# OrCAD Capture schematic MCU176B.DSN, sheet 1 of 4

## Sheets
1 1_RF: size A3; title: LP-EM-CC2755P20
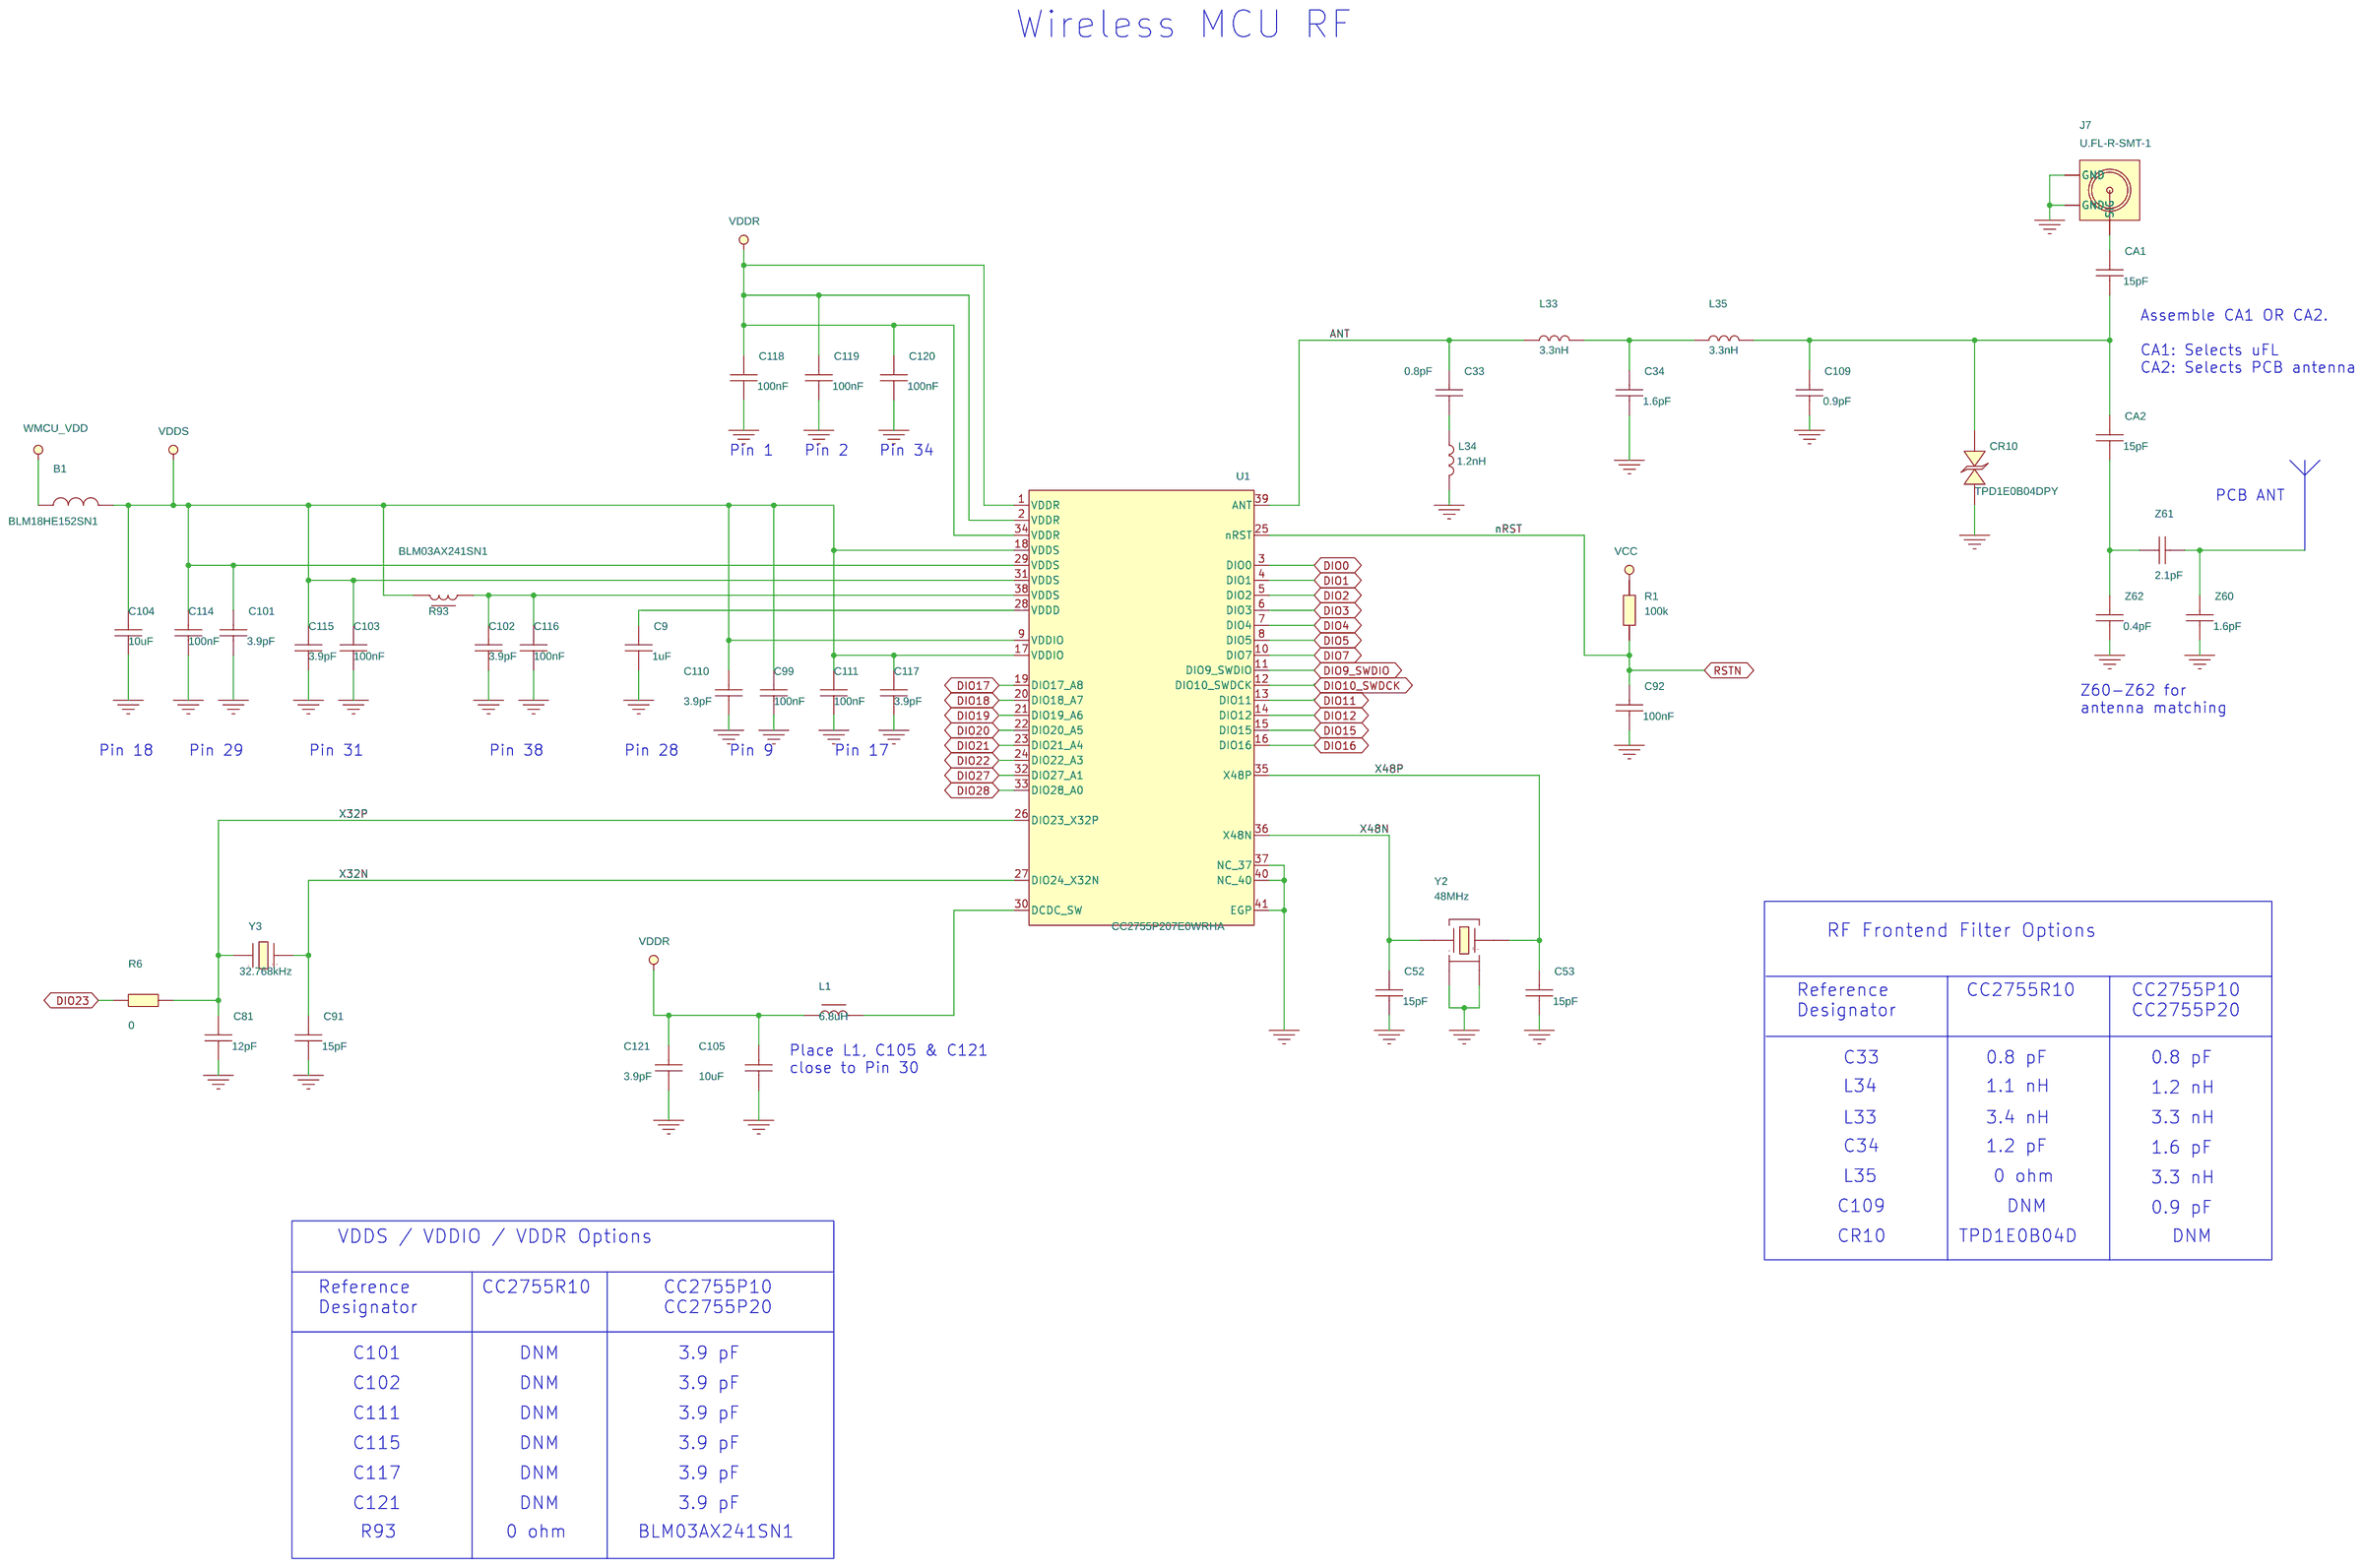
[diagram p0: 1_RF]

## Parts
B1  BLM18HE152SN1  [FIL_BLM18HE152SN1DN]
C9  1uF  [CAPC1005X60A2N]
C33  0.8pF  [CAPC0603X35B2N]
C34  1.6pF  [CAPC0603X35B2N]
C52  15pF  [CAPC0603X35B2N]
C53  15pF  [CAPC0603X35B2N]
C81  12pF  [CAPC0603X35B2N]
C91  15pF  [CAPC0603X35B2N]
C92  100nF  [CAPC0603X35B2N]
C99  100nF  [CAPC0603X35B2N]
C101  3.9pF  [CAPC0603X35B2N]
C102  3.9pF  [CAPC0603X35B2N]
C103  100nF  [CAPC0603X35B2N]
C104  10uF  [CAPC1608X100A2N]
C105  10uF  [CAPC1608X100A2N]
C109  0.9pF  [CAPC0603X35B2N]
C110  3.9pF  [CAPC0603X35B2N]
C111  100nF  [CAPC0603X35B2N]
C114  100nF  [CAPC0603X35B2N]
C115  3.9pF  [CAPC0603X35B2N]
C116  100nF  [CAPC0603X35B2N]
C117  3.9pF  [CAPC0603X35B2N]
C118  100nF  [CAPC0603X35B2N]
C119  100nF  [CAPC0603X35B2N]
C120  100nF  [CAPC0603X35B2N]
C121  3.9pF  [CAPC0603X35B2N]
CA1  15pF  [CAPC0603X35B2N]
CA2  15pF  [CAPC0603X35B2N]
CR10  TPD1E0B04DPY  [SON65P100X60X45-2A2N]
J7  U.FL-R-SMT-1  [HIROSE_UFLRSMT_A2N]
L1  6.8uH  [INDC2012X150A2N]
L33  3.3nH  [INDC0603X33A2N]
L34  1.2nH  [INDC0603X33A2N]
L35  3.3nH  [INDC0603X33A2N]
R1  100k  [RESC0603X35B2N]
R6  0  [RESC0603X35B2N]
R93  BLM03AX241SN1  [FILC0603X33A2N]
U1  CC2755P207E0WRHA  [QFNFC50P600X600X100-41C2N]
Y2  48MHz  [OSCCC200X160X50-4B2N]
Y3  32.768kHz  [XTAL_FC2012AA_A2N]
Z60  1.6pF  [CAPC0603X35B2N]
Z61  2.1pF  [CAPC0603X35B2N]
Z62  0.4pF  [CAPC0603X35B2N]

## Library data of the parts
B1 = FILTER_2PIN: FILTER, EMI, FERRITE BEAD, 1.5k@100MHz, -25%/+25%, -55DEGC/+125DEGC, 0603, SMD; ALT_SYMBOLS: FIL_BLM18HE152SN1DL,FIL_BLM18HE152SN1DM; Additional Datasheet URL: https://pim.murata.com/en-us/pim/details?partNum=BLM18HE152SN1%23; Budgetary Price: .07 EUR; CLASS: DISCRETE; Country of Origin: Japan; Datasheet URL: https://pim.murata.com/asset/pim4/ferriteBeadInductortypefilter/ENFA0004_PDF_FERRITEBEADINDUCTORTYPEFILTER?lastModifiedDatetime=20250707191219; Frequency: 100MHz; Impedance: 1.5k; Inductance: N/A; Lead Time: 8; Mass: 0.006g; Maximum Operating Temperature: +125DEGC; Maximum Tolerance: +25%; Minimum Operating Temperature: -55DEGC; Minimum Tolerance: -25%; Mounting Type: SMD; NOTEfied URL: https://webinterface.notefied-dynamic-precision.com/item/7304126; PCB Package: 0603; Packing Size: 4000; Packing Type: Tape & Reel; Part Number: 04-00470; Part Type: Filter|EMI|FERRITE BEAD|0603; REACH/SVHC Compliance: Compliant; REACH/SVHC Details: SVHC List Version Jan 23, 2024 (240); REACH/SVHC Source: REACH Declaration; REACH/SVHC Status: Unaffected; ROHS: Compliant; Rated Current: 0.5A; Rated Voltage: N/A; Status: Released; Texas Part Status: Under Review; Type: Filter; Vendor: MURATA; Vendor Part Number: BLM18HE152SN1D; Vendor Part Status: Active
C9 = CAPACITOR: CAPACITOR, CERAMIC X7R, 1uF, -10%/+10%, 10V, -55DEGC/+125DEGC, 0402, SMD; ALT_SYMBOLS: CAPC1005X60A2L,CAPC1005X60A2M; Additional Datasheet URL: https://pim.murata.com/en-us/pim/details?partNum=GRM155Z71A105KE01%23; Budgetary Price: .01854 USD; Country of Origin: China, Japan, Philippines, Singapore, Thailand; Datasheet URL: https://pim.murata.com/asset/pim4/ceramicCapacitorSMD/GRM155Z71A105KE01-01A-EN_PDF_CERAMICCAPACITORSMD?lastModifiedDatetime=20250813144905; Dielectric Type: X7R; FPLIST: CAPC1005X60A2N,CAPC1005X60B2N; Lead Time: 12; Mass: 0.0016g; Maximum Operating Temperature: +125DEGC; Maximum Tolerance: +10%; Minimum Operating Temperature: -55DEGC; Minimum Tolerance: -10%; Mounting Type: SMD; NOTEfied URL: https://webinterface.notefied-dynamic-precision.com/item/34840285; PCB Package: 0402; Packing Size: 10000; Packing Type: Tape & Reel; Part Number: 02-10417; Part Type: Capacitor|CERAMIC|0402|STANDARD; REACH/SVHC Compliance: Compliant; REACH/SVHC Details: SVHC List Version Jan 23, 2024 (240); REACH/SVHC Source: REACH Declaration; REACH/SVHC Status: Unaffected; ROHS: Compliant; Rated Voltage: 10V; Status: Released; Texas Part Status: Under Review; Type: Capacitor; Vendor: MURATA; Vendor Part Number: GRM155Z71A105KE01D; Vendor Part Status: Active
C33 = CAPACITOR: CAPACITOR, CERAMIC C0G/NP0, 0.8pF, -0.1pF/+0.1pF, 50V, -55DEGC/+125DEGC, 0201, SMD; ALT_SYMBOLS: CAPC0603X35B2L,CAPC0603X35B2M; Additional Datasheet URL: https://pim.murata.com/en-us/pim/details?partNum=GRM0335C1HR80BA01%23; Budgetary Price: .00272 USD; Country of Origin: China, Japan, Philippines, Singapore, Thailand; Datasheet URL: https://pim.murata.com/asset/pim4/ceramicCapacitorSMD/GRM0335C1HR80BA01-01A-EN_PDF_CERAMICCAPACITORSMD?lastModifiedDatetime=20250813140832; Dielectric Type: C0G/NP0; Lead Time: 11; Mass: 0.00033g; Maximum Operating Temperature: +125DEGC; Maximum Tolerance: +0.1pF; Minimum Operating Temperature: -55DEGC; Minimum Tolerance: -0.1pF; Mounting Type: SMD; NOTEfied URL: https://webinterface.notefied-dynamic-precision.com/item/7272565; PCB Package: 0201; Packing Size: 50000; Packing Type: Tape & Reel; Part Number: 02-06122; Part Type: Capacitor|CERAMIC|0201|STANDARD; REACH/SVHC Compliance: Compliant; REACH/SVHC Details: SVHC List Version Jan 23, 2024 (240); REACH/SVHC Source: REACH Declaration; REACH/SVHC Status: Unaffected; ROHS: Compliant; Rated Voltage: 50V; Status: Released; Texas Part Status: Under Review; Type: Capacitor; Vendor: MURATA; Vendor Part Number: GRM0335C1HR80BA01J; Vendor Part Status: Active
C34 Z60 = CAPACITOR: CAPACITOR, CERAMIC C0G/NP0, 1.6pF, -0.1pF/+0.1pF, 50V, -55DEGC/+125DEGC, 0201, SMD; ALT_SYMBOLS: CAPC0603X35B2L,CAPC0603X35B2M; Additional Datasheet URL: https://pim.murata.com/en-us/pim/details?partNum=GRM0335C1H1R6BA01%23; Budgetary Price: .00215 USD; Country of Origin: China, Japan, Philippines, Singapore, Thailand; Datasheet URL: https://pim.murata.com/asset/pim4/ceramicCapacitorSMD/GRM0335C1H1R6BA01-01A-EN_PDF_CERAMICCAPACITORSMD?lastModifiedDatetime=20250813140550; Dielectric Type: C0G/NP0; Lead Time: 84; Mass: 0.00033g; Maximum Operating Temperature: +125DEGC; Maximum Tolerance: +0.1pF; Minimum Operating Temperature: -55DEGC; Minimum Tolerance: -0.1pF; Mounting Type: SMD; NOTEfied URL: https://webinterface.notefied-dynamic-precision.com/item/7272585; PCB Package: 0201; Packing Size: 50000; Packing Type: Tape & Reel; Part Number: 02-06130; Part Type: Capacitor|CERAMIC|0201|STANDARD; REACH/SVHC Compliance: Compliant; REACH/SVHC Details: SVHC List Version Jan 23, 2024 (240); REACH/SVHC Source: REACH Declaration; REACH/SVHC Status: Unaffected; ROHS: Compliant; Rated Voltage: 50V; Status: Released; Texas Part Status: Under Review; Type: Capacitor; Vendor: MURATA; Vendor Part Number: GRM0335C1H1R6BA01J; Vendor Part Status: Active
C52 C53 C91 = CAPACITOR: CAPACITOR, CERAMIC C0G/NP0, 15pF, -2%/+2%, 50V, -55DEGC/+125DEGC, 0201, SMD; ALT_SYMBOLS: CAPC0603X35B2L,CAPC0603X35B2M; Additional Datasheet URL: https://pim.murata.com/en-us/pim/details?partNum=GRM0335C1H150GA01%23; Budgetary Price: .0032 USD; Country of Origin: China, Japan, Philippines, Singapore, Thailand; Datasheet URL: https://pim.murata.com/asset/pim4/ceramicCapacitorSMD/GRM0335C1H150GA01-01A-EN_PDF_CERAMICCAPACITORSMD?lastModifiedDatetime=20250813140536; Dielectric Type: C0G/NP0; Lead Time: 11; Mass: 0.00033g; Maximum Operating Temperature: +125DEGC; Maximum Tolerance: +2%; Minimum Operating Temperature: -55DEGC; Minimum Tolerance: -2%; Mounting Type: SMD; NOTEfied URL: https://webinterface.notefied-dynamic-precision.com/item/20744949; PCB Package: 0201; Packing Size: 15000; Packing Type: Tape & Reel; Part Number: 02-09323; Part Type: Capacitor|CERAMIC|0201|STANDARD; REACH/SVHC Compliance: Compliant; REACH/SVHC Details: SVHC List Version Jan 23, 2024 (240); REACH/SVHC Source: REACH Declaration; REACH/SVHC Status: Unaffected; ROHS: Compliant; Rated Voltage: 50V; Status: Released; Texas Part Status: Under Review; Type: Capacitor; Vendor: MURATA; Vendor Part Number: GRM0335C1H150GA01D; Vendor Part Status: Active
C81 = CAPACITOR: CAPACITOR, CERAMIC C0G/NP0, 12pF, -5%/+5%, 50V, -55DEGC/+125DEGC, 0201, SMD; ALT_SYMBOLS: CAPC0603X35B2L,CAPC0603X35B2M; Additional Datasheet URL: https://pim.murata.com/en-us/pim/details?partNum=GRM0335C1H120JA01%23; Budgetary Price: .0024 USD; Country of Origin: China, Japan, Philippines, Singapore, Thailand; Datasheet URL: https://pim.murata.com/asset/pim4/ceramicCapacitorSMD/GRM0335C1H120JA01-01A-EN_PDF_CERAMICCAPACITORSMD?lastModifiedDatetime=20250813140532; Dielectric Type: C0G/NP0; Lead Time: 11; Mass: 0.00033g; Maximum Operating Temperature: +125DEGC; Maximum Tolerance: +5%; Minimum Operating Temperature: -55DEGC; Minimum Tolerance: -5%; Mounting Type: SMD; NOTEfied URL: https://webinterface.notefied-dynamic-precision.com/item/20764951; PCB Package: 0201; Packing Size: 15000; Packing Type: Tape & Reel; Part Number: 02-09326; Part Type: Capacitor|CERAMIC|0201|STANDARD; REACH/SVHC Compliance: Compliant; REACH/SVHC Details: SVHC List Version Jan 23, 2024 (240); REACH/SVHC Source: REACH Declaration; REACH/SVHC Status: Unaffected; ROHS: Compliant; Rated Voltage: 50V; Status: Released; Texas Part Status: Under Review; Type: Capacitor; Vendor: MURATA; Vendor Part Number: GRM0335C1H120JA01D; Vendor Part Status: Active
C92 C99 C103 C111 C114 C116 C118-C120 = CAPACITOR: CAPACITOR, CERAMIC X7S, 100nF, -10%/+10%, 16V, -55DEGC/+125DEGC, 0201, SMD; ALT_SYMBOLS: CAPC0603X35B2L,CAPC0603X35B2M; Additional Datasheet URL: https://pim.murata.com/en-us/pim/details?partNum=GRM033C71C104KE14%23; Budgetary Price: .00785 EUR; Country of Origin: China, Japan, Philippines, Singapore, Thailand; Datasheet URL: https://pim.murata.com/asset/pim4/ceramicCapacitorSMD/GRM033C71C104KE14-01A-EN_PDF_CERAMICCAPACITORSMD?lastModifiedDatetime=20250813141327; Dielectric Type: X7S; Lead Time: 11; Mass: 0.00033g; Maximum Operating Temperature: +125DEGC; Maximum Tolerance: +10%; Minimum Operating Temperature: -55DEGC; Minimum Tolerance: -10%; Mounting Type: SMD; NOTEfied URL: https://webinterface.notefied-dynamic-precision.com/item/20463738; PCB Package: 0201; Packing Size: 15000; Packing Type: Tape & Reel; Part Number: 02-09228; Part Type: Capacitor|CERAMIC|0201|STANDARD; REACH/SVHC Compliance: Compliant; REACH/SVHC Details: SVHC List Version Jan 23, 2024 (240); REACH/SVHC Source: REACH Declaration & Material Declaration; REACH/SVHC Status: Unaffected; ROHS: Compliant; Rated Voltage: 16V; Status: Released; Texas Part Number: TEXAS_00001; Texas Part Status: Under Review; Type: Capacitor; Vendor: MURATA; Vendor Part Number: GRM033C71C104KE14D; Vendor Part Status: Active
C101 C102 C110 C115 C117 C121 = CAPACITOR: CAPACITOR, CERAMIC C0G/NP0, 3.9pF, -0.25pF/+0.25pF, 25V, -55DEGC/+125DEGC, 0201, SMD; ALT_SYMBOLS: CAPC0603X35B2L,CAPC0603X35B2M; Additional Datasheet URL: https://search.kyocera-avx.com/product/KGM03ACG1E3R9CH; Budgetary Price: .09832 USD; Country of Origin: Missing Info; Datasheet URL: https://datasheets.kyocera-avx.com/C0GNP0-KGM.pdf; Dielectric Type: C0G/NP0; Lead Time: 16; Mass: 0.000228g; Maximum Operating Temperature: +125DEGC; Maximum Tolerance: +0.25pF; Minimum Operating Temperature: -55DEGC; Minimum Tolerance: -0.25pF; Mounting Type: SMD; NOTEfied URL: https://webinterface.notefied-dynamic-precision.com/item/7266918; Notes: Old ordering code: 02013A3R9CAT2A.; PCB Package: 0201; Packing Size: 15000; Packing Type: Tape & Reel; Part Number: 02-04271; Part Type: Capacitor|CERAMIC|0201|STANDARD; ROHS: Compliant; Rated Voltage: 25V; Status: Released; Type: Capacitor; Vendor: KYOCERA AVX; Vendor Part Number: KGM03ACG1E3R9CH; Vendor Part Status: Active
C104 C105 = CAPACITOR: CAPACITOR, CERAMIC X7T, 10uF, -20%/+20%, 10V, -55DEGC/+125DEGC, 0603, SMD; ALT_SYMBOLS: CAPC1608X100A2L,CAPC1608X100A2M; Additional Datasheet URL: https://pim.murata.com/en-us/pim/details?partNum=GRM188D71A106MA73%23; Country of Origin: China, Japan, Philippines, Singapore, Thailand; Datasheet URL: https://pim.murata.com/asset/pim4/ceramicCapacitorSMD/GRM188D71A106MA73-01A-EN_PDF_CERAMICCAPACITORSMD?lastModifiedDatetime=20250813150623; Dielectric Type: X7T; Mass: 0.0091g; Maximum Operating Temperature: +125DEGC; Maximum Tolerance: +20%; Minimum Operating Temperature: -55DEGC; Minimum Tolerance: -20%; Mounting Type: SMD; NOTEfied URL: https://webinterface.notefied-dynamic-precision.com/item/46681190; PCB Package: 0603; Packing Size: 4000; Packing Type: Tape & Reel; Part Number: 02-10942; Part Type: Capacitor|CERAMIC|0603|STANDARD; REACH/SVHC Details: SVHC List Version; ROHS: Compliant; Rated Voltage: 10V; Status: Released; Type: Capacitor; Vendor: MURATA; Vendor Part Number: GRM188D71A106MA73D; Vendor Part Status: Active
C109 = CAPACITOR: CAPACITOR, CERAMIC C0G/NP0, 0.9pF, -0.1pF/+0.1pF, 50V, -55DEGC/+125DEGC, 0201, SMD; ALT_SYMBOLS: CAPC0603X35B2L,CAPC0603X35B2M; Additional Datasheet URL: https://pim.murata.com/en-us/pim/details?partNum=GRM0335C1HR90BA01%23; Budgetary Price: .002 USD; Country of Origin: China, Japan, Philippines, Singapore, Thailand; Datasheet URL: https://pim.murata.com/asset/pim4/ceramicCapacitorSMD/GRM0335C1HR90BA01-01A-EN_PDF_CERAMICCAPACITORSMD?lastModifiedDatetime=20250813140833; Dielectric Type: C0G/NP0; Lead Time: 11; Mass: 0.00033g; Maximum Operating Temperature: +125DEGC; Maximum Tolerance: +0.1pF; Minimum Operating Temperature: -55DEGC; Minimum Tolerance: -0.1pF; Mounting Type: SMD; NOTEfied URL: https://webinterface.notefied-dynamic-precision.com/item/7272566; PCB Package: 0201; Packing Size: 50000; Packing Type: Tape & Reel; Part Number: 02-06123; Part Type: Capacitor|CERAMIC|0201|STANDARD; REACH/SVHC Compliance: Compliant; REACH/SVHC Details: SVHC List Version Jan 23, 2024 (240); REACH/SVHC Source: REACH Declaration; REACH/SVHC Status: Unaffected; ROHS: Compliant; Rated Voltage: 50V; Status: Released; Texas Part Status: Under Review; Type: Capacitor; Vendor: MURATA; Vendor Part Number: GRM0335C1HR90BA01J; Vendor Part Status: Active
CA1 CA2 = CAPACITOR: CAPACITOR, CERAMIC CH(JIS), 15pF, -5%/+5%, 50V, -55DEGC/+125DEGC, 0201, SMD; ALT_SYMBOLS: CAPC0603X35B2L,CAPC0603X35B2M; Additional Datasheet URL: https://www.murata.com/en-us/products/productdetail?partno=GRM0332C1H150JA01%23; Country of Origin: China, Philippines; Datasheet URL: https://search.murata.co.jp/Ceramy/image/img/A01X/G101/ENG/GRM0332C1H150JA01-01A.pdf; Dielectric Type: CH(JIS); Mass: 0.00033g; Maximum Operating Temperature: +125DEGC; Maximum Tolerance: +5%; Minimum Operating Temperature: -55DEGC; Minimum Tolerance: -5%; Mounting Type: SMD; NOTEfied URL: https://webinterface.notefied-dynamic-precision.com/item/7272608; PCB Package: 0201; Packing Size: 15000; Packing Type: Tape & Reel; Part Number: 02-06059; Part Type: Capacitor|CERAMIC|0201|STANDARD; ROHS: Compliant; Rated Voltage: 50V; Status: Released; Type: Capacitor; Vendor: MURATA; Vendor Part Number: GRM0332C1H150JA01D; Vendor Part Status: Active
CR10 = DIODE_TVS_BIDIR_S: DIODE, PROTECTION, TVS, BID, 6.7V, 15W, -40DEGC/+125DEGC, X1SON2, SMD; Additional Datasheet URL: https://www.ti.com/product/TPD1E0B04; AutoDoc File: https://notefied-dynamic-precision.com/DB/Apps/Desktop/Item/Object.aspx?id=118028; BU Name: DYNAMIC PRECISION GDANSK; Budget Currency: USD; Budget Price: 0.08; Budgetary Price: .144 USD; Client Status: UNDER_REVIEW; Country of Origin: China, Philippines; Datasheet URL: https://www.ti.com/lit/gpn/TPD1E0B04; Datasheet URL 1: http://www.ti.com/lit/ds/symlink/tpd1e0b04.pdf; Datasheet URL 2: http://www.ti.com/lit/ml/mpss034c/mpss034c.pdf; Lead Time: 12; Mass: 0.0031g; Max Oper Temp: +125DEGC; Maximum Operating Temperature: +125DEGC; Min Oper Temp: -40DEGC; Minimum Operating Temperature: -40DEGC; Mounting Type: SMD; NOTEfied URL: https://webinterface.notefied-dynamic-precision.com/item/12481442; PCB Package: SON2; Packing Size: 10000; Packing Type: Tape & Reel; Part Number: 14-06704; Part Type: Diode|PROTECTION; REACH/SVHC Compliance: Compliant; REACH/SVHC Details: SVHC List Version Jan 12, 2017 (173); REACH/SVHC Source: REACH Declaration; REACH/SVHC Status: Unaffected; ROHS: Compliant; Rated Power: 15W; Rated Voltage: 6.7V; Revision: R027; RoHS Status: ROHS_COMPLIANT; Rtd Power: 15W; Rtd Voltage: 6.7V; Status: Released; Texas Part Status: Under Review; Type: Diode; Vendor: TEXAS INSTRUMENTS; Vendor Part Number: TPD1E0B04DPYR; Vendor Part Status: Active; Weight: 0.0031g
J7 = CONN_COAX_1_P_2_UFL: CONNECTOR, COAX, RF, MALE, STRAIGHT, 1 PIN(S), SMD; ALT_SYMBOLS: HIROSE_UFLRSMT_A2L,HIROSE_UFLRSMT_A2M; Additional Datasheet URL: https://www.hirose.com/en/product/p/CL0331-0472-2-01; Budgetary Price: .7575 USD; CLASS: IO; Country of Origin: China, Japan; Datasheet URL: https://www.hirose.com/en/product/document?clcode=CL0331-0472-2-01&productname=U.FL-R-SMT-1(01)&series=U.FL&documenttype=Catalog&lang=en&documentid=ed_U.FL_CAT; Lead Time: 12; Mass: 0.0157g; Maximum Operating Temperature: +105DEGC; Minimum Operating Temperature: -40DEGC; Mounting Type: SMD; NOTEfied URL: https://webinterface.notefied-dynamic-precision.com/item/7312664; Number of Positions: 1; Packing Size: 100; Packing Type: Bag; Part Number: 06-01471; Part Type: Connector|COAX|RF; ROHS: Compliant; Rated Voltage: 200V; Status: Released; Type: Connector; Vendor: HIROSE; Vendor Part Number: U.FL-R-SMT-1(01); Vendor Part Status: Active
L1 = IND_CORE: INDUCTOR, STANDARD, FERRITE CORE, SHIELDED, 6.8uH, -20%/+20%, 0.11A, -55DEGC/+125DEGC, 0805, SMD; ALT_SYMBOLS: INDC2012X150A2L,INDC2012X150A2M; Additional Datasheet URL: https://product.tdk.com/en/search/inductor/inductor/smd/info?part_no=MLZ2012N6R8LTD25; Budgetary Price: .069 EUR; Country of Origin: Missing Info; Datasheet URL: https://product.tdk.com/system/files/dam/doc/product/inductor/inductor/smd/catalog/inductor_automotive_decoupling_mlz2012_en.pdf; Lead Time: 11; Mass: 0.01g; Maximum Operating Temperature: +125DEGC; Maximum Tolerance: +20%; Minimum Operating Temperature: -55DEGC; Minimum Tolerance: -20%; Mounting Type: SMD; NOTEfied URL: https://webinterface.notefied-dynamic-precision.com/item/18805989; PCB Package: 0805; Packing Size: 4000; Packing Type: Tape & Reel; Part Number: 03-07971; Part Type: Inductor|STANDARD|CHIP|0805; REACH/SVHC Compliance: Compliant; REACH/SVHC Details: SVHC List Version Jun 27, 2018 (191); REACH/SVHC Source: REACH Declaration; REACH/SVHC Status: Unaffected; ROHS: Compliant; Rated Current: 0.11A; Resistance: 0.25; Status: Released; Texas Part Status: Under Review; Type: Inductor; Vendor: TDK; Vendor Part Number: MLZ2012N6R8LTD25; Vendor Part Status: Active
L33 L35 = INDUCTOR: INDUCTOR, RF, CHIP, NON-MAGNETIC CORE, UNSHIELDED, 3.3nH, -0.1nH/+0.1nH, 0.45A, -55DEGC/+125DEGC, 0201, SMD; ALT_SYMBOLS: INDC0603X33A2L,INDC0603X33A2M; Additional Datasheet URL: https://pim.murata.com/en-us/pim/details?partNum=LQP03TN3N3B02%23; Country of Origin: Missing Info; Datasheet URL: https://pim.murata.com/asset/pim4/inductor/JELF243C-0015_PDF_INDUCTOR?lastModifiedDatetime=20250708072121; Frequency: 8GHz; Mass: 0.0002g; Maximum Operating Temperature: +125DEGC; Maximum Tolerance: +0.1nH; Minimum Operating Temperature: -55DEGC; Minimum Tolerance: -0.1nH; Mounting Type: SMD; NOTEfied URL: https://webinterface.notefied-dynamic-precision.com/item/7300390; PCB Package: 0201; Packing Size: 50000; Packing Type: Tape & Reel; Part Number: 03-06936; Part Type: Inductor|RF|CHIP|0201; REACH/SVHC Compliance: Compliant; REACH/SVHC Details: SVHC List Version Jan 23, 2024 (240); REACH/SVHC Source: REACH Declaration; REACH/SVHC Status: Unaffected; ROHS: Compliant; Rated Current: 0.45A; Resistance: 0.25; Status: Released; Texas Part Status: Under Review; Type: Inductor; Vendor: MURATA; Vendor Part Number: LQP03TN3N3B02J; Vendor Part Status: Active
L34 = INDUCTOR: INDUCTOR, RF, CHIP, NON-MAGNETIC CORE, UNSHIELDED, 1.2nH, -0.1nH/+0.1nH, 0.75A, -55DEGC/+125DEGC, 0201, SMD; ALT_SYMBOLS: INDC0603X33A2L,INDC0603X33A2M; Additional Datasheet URL: https://pim.murata.com/en-us/pim/details?partNum=LQP03TN1N2BZ2%23; Budgetary Price: .02095 USD; Country of Origin: Missing Info; Datasheet URL: https://pim.murata.com/asset/pim4/inductor/JELF243C-9101_PDF_INDUCTOR?lastModifiedDatetime=20250708072122; Frequency: 17GHz; Lead Time: 106; Mass: 0.0002g; Maximum Operating Temperature: +125DEGC; Maximum Tolerance: +0.1nH; Minimum Operating Temperature: -55DEGC; Minimum Tolerance: -0.1nH; Mounting Type: SMD; NOTEfied URL: https://webinterface.notefied-dynamic-precision.com/item/35969682; PCB Package: 0201; Packing Size: 15000; Packing Type: Tape & Reel; Part Number: 03-08412; Part Type: Inductor|RF|CHIP|0201; REACH/SVHC Compliance: Compliant; REACH/SVHC Details: SVHC List Version Jan 23, 2024 (240); REACH/SVHC Source: REACH Declaration; REACH/SVHC Status: Unaffected; ROHS: Compliant; Rated Current: 0.75A; Resistance: 0.1; Status: Released; Texas Part Status: Under Review; Type: Inductor; Vendor: MURATA; Vendor Part Number: LQP03TN1N2BZ2D; Vendor Part Status: Active
R1 = RESISTOR: RESISTOR, THICK FILM, 100k, -5%/+5%, 0.05W, 30V, -55DEGC/+155DEGC, 0201, SMD; ALT_SYMBOLS: RESC0603X35B2L,RESC0603X35B2M; Additional Datasheet URL: https://www.vishay.com/en/product/20052/; Budgetary Price: .005 EUR; Country of Origin: China, Malaysia; Datasheet URL: https://www.vishay.com/docs/20052/crcw0201e3.pdf; Lead Time: 20; Mass: 0.00017g; Maximum Operating Temperature: +155DEGC; Maximum Temperature Coefficient: +200PPM/DEGC; Maximum Tolerance: +5%; Minimum Operating Temperature: -55DEGC; Minimum Temperature Coefficient: -200PPM/DEGC; Minimum Tolerance: -5%; Mounting Type: SMD; NOTEfied URL: https://webinterface.notefied-dynamic-precision.com/item/7195810; PCB Package: 0201; Packing Size: 10000; Packing Type: Tape & Reel; Part Number: 01-04220; Part Type: Resistor|0201|STANDARD; REACH/SVHC Compliance: Compliant; REACH/SVHC Details: SVHC List Version Jan 23, 2024 (240); REACH/SVHC Source: REACH Declaration & Material Declaration; REACH/SVHC Status: Unaffected; ROHS: Exempt; Rated Current: N/A; Rated Power: 0.05W; Rated Voltage: 30V; Resistor Type: THICK FILM; Status: Released; Texas Part Number: TEXAS_00013; Texas Part Status: Under Review; Type: Resistor; Vendor: VISHAY; Vendor Part Number: CRCW0201100KJNED; Vendor Part Status: Active
R6 = RESISTOR: RESISTOR, THICK FILM, JUMPER, 0, 0R/+0.05R, 0.5A, -55DEGC/+125DEGC, 0201, SMD; ALT_SYMBOLS: RESC0603X35B2L,RESC0603X35B2M; Additional Datasheet URL: https://www.koaspeer.com/products/resistors/general-purpose/rk73z/; Budgetary Price: .012 EUR; Country of Origin: Missing Info; Datasheet URL: https://www.koaspeer.com/pdfs/RK73Z.pdf; Lead Time: 14; Mass: 0.00014g; Maximum Operating Temperature: +125DEGC; Maximum Temperature Coefficient: N/A; Maximum Tolerance: +0.05R; Minimum Operating Temperature: -55DEGC; Minimum Temperature Coefficient: N/A; Minimum Temperature Coeficient: N/A; Minimum Tolerance: 0R; Mounting Type: SMD; NOTEfied URL: https://webinterface.notefied-dynamic-precision.com/item/7239994; PCB Package: 0201; Packing Size: 10000; Packing Type: Tape & Reel; Part Number: 01-18293; Part Type: Resistor|0201|JUMPER; ROHS: Exempt; Rated Current: 0.5A; Rated Power: N/A; Rated Voltage: N/A; Resistor Type: THICK FILM; Revision: R014; Status: Released; Type: Resistor; Vendor: KOA SPEER; Vendor Part Number: RK73Z1HTTC; Vendor Part Status: NRND
R93 = FILTER_FERRITE: FILTER, EMI, FERRITE BEAD, 240@100MHz, -25%/+25%, -55DEGC/+125DEGC, 0201, SMD; ALT_SYMBOLS: FILC0603X33A2L,FILC0603X33A2M; Additional Datasheet URL: https://pim.murata.com/en-us/pim/details?partNum=BLM03AX241SN1%23; Budgetary Price: .03958 USD; CLASS: DISCRETE; Country of Origin: Thailand; Datasheet URL: https://pim.murata.com/asset/pim4/ferriteBeadInductortypefilter/ENFA0020_PDF_FERRITEBEADINDUCTORTYPEFILTER?lastModifiedDatetime=20250707191113; Frequency: 100MHz; Impedance: 240; Inductance: N/A; Lead Time: 9; Mass: 0.0003g; Maximum Operating Temperature: +125DEGC; Maximum Tolerance: +25%; Minimum Operating Temperature: -55DEGC; Minimum Tolerance: -25%; Mounting Type: SMD; NOTEfied URL: https://webinterface.notefied-dynamic-precision.com/item/7305433; PCB Package: 0201; Packing Size: 15000; Packing Type: Tape & Reel; Part Number: 04-00855; Part Type: Filter|EMI|FERRITE BEAD|0201; ROHS: Compliant; Rated Current: 0.35A; Resistance: 0.38; Status: Released; Type: Filter; Vendor: MURATA; Vendor Part Number: BLM03AX241SN1D; Vendor Part Status: Active
U1 = IC_PROC_CC2755_VQFN40: IC, MICROCONTROLLER, ARM CORTEX M33, CC2755, 32-bit, VQFN40-EP, SMD; ALT_SYMBOLS: QFNFC50P600X600X100-41C2L,QFNFC50P600X600X100-41C2M; Additional Datasheet URL: https://www.ti.com/product-category/wireless-connectivity/low-power-2-4-ghz/overview.html; Country of Origin: Missing Info; Datasheet URL: N/A; Mass: N/A; Maximum Operating Temperature: N/A; Minimum Operating Temperature: N/A; Mounting Type: SMD; NOTEfied URL: https://webinterface.notefied-dynamic-precision.com/item/70437855; Notes: The datasheet for the CC2755P20 series is not avaiable yet. The component is pin-to-pin compatible with CC2755P105E0WRHA; PCB Package: VQFN40-EP; Packing Size: N/A; Packing Type: Missing Info; Part Number: 18-40198; Part Type: IC|MICROCONTROLLER|TEXAS INSTRUMENTS; REACH/SVHC Compliance: Missing Info; REACH/SVHC Details: N/A; REACH/SVHC Source: N/A; REACH/SVHC Status: Missing Info; ROHS: Missing Info; Status: Released; Texas Part Status: Under Review; Type: IC; Vendor: TEXAS INSTRUMENTS; Vendor Part Number: CC2755P205E0WRHA; Vendor Part Status: Preliminary
Y2 = XTAL_4_V5: CRYSTAL, RESONATOR, 48MHz, -85PPM/+85PPM, -40DEGC/+125DEGC, 2016, SMD; ALT_SYMBOLS: OSCCC200X160X50-4B2L,OSCCC200X160X50-4B2M; Additional Datasheet URL: https://www.ndk.com/en/products/lineup/crystal-unit/NX2016SA-vehicle.html; Capacitance: 7pF; Country of Origin: Missing Info; Datasheet URL: N/A; Mass: N/A; Maximum Operating Temperature: +125DEGC; Maximum Stability: +85PPM; Maximum Tolerance: +10PPM; Minimum Operating Temperature: -40DEGC; Minimum Stability: -85PPM; Minimum Tolerance: -10PPM; Mounting Type: SMD; NOTEfied URL: https://webinterface.notefied-dynamic-precision.com/item/7336003; Notes: Custom item:Documentation specified for the client; PCB Package: 2016; Packing Size: 3000; Packing Type: Tape & Reel; Part Number: 12-01232; Part Type: Crystal|RESONATOR; REACH/SVHC Compliance: Compliant; REACH/SVHC Details: SVHC List Version Jun 20, 2016 (169); REACH/SVHC Source: REACH Declaration; REACH/SVHC Status: Unaffected; ROHS: Compliant; Rated Voltage: N/A; Status: Released; Texas Part Status: Under Review; Type: Crystal; Vendor: NIHON DEMPA KOGYO; Vendor Part Number: NX2016SA 48.000MHz EXS00A-CS05517; Vendor Part Status: Active
Y3 = XTAL: CRYSTAL, RESONATOR, 32.768kHz, -40DEGC/+125DEGC, 2012, SMD; ALT_SYMBOLS: XTAL_FC2012AA_A2L,XTAL_FC2012AA_A2M; Additional Datasheet URL: https://www.epsondevice.com/crystal/en/products/crystal-unit/fc2012aa.html; Capacitance: 7pF; Country of Origin: Missing Info; Datasheet URL: https://download.epsondevice.com/td/pdf/app/FC2012AA_en.pdf; Mass: 0.0042g; Maximum Operating Temperature: +125DEGC; Maximum Stability: N/A; Maximum Tolerance: +20PPM; Minimum Operating Temperature: -40DEGC; Minimum Stability: N/A; Minimum Tolerance: -20PPM; Mounting Type: SMD; NOTEfied URL: https://webinterface.notefied-dynamic-precision.com/item/56333469; Notes: Alias pns: X1A000181000318, FC2012AA 32.768000kHz 7 +20.0-20.0; PCB Package: 2012; Packing Size: 5000; Packing Type: Tape & Reel; Part Number: 12-01782; Part Type: Crystal|RESONATOR; REACH/SVHC Compliance: Compliant; REACH/SVHC Details: SVHC List Version Jan 23, 2024 (240); REACH/SVHC Source: REACH Declaration; REACH/SVHC Status: Unaffected; ROHS: Compliant; Revision: R001; Status: Released; Texas Part Status: Under Review; Type: Crystal; Vendor: EPSON; Vendor Part Number: FC2012AA 32.768K-70NN75KC7; Vendor Part Status: Active
Z61 = CAPACITOR: CAPACITOR, CERAMIC C0G/NP0, 2.1pF, -0.1pF/+0.1pF, 50V, -55DEGC/+125DEGC, 0201, SMD; ALT_SYMBOLS: CAPC0603X35B2L,CAPC0603X35B2M; Additional Datasheet URL: https://pim.murata.com/en-us/pim/details/?productCategoryId=ceramicCapacitorSMD&partNum=GRM0335C1H2R1BA01%23; Budgetary Price: .004 EUR; Country of Origin: China, Japan, Philippines, Singapore, Thailand; Datasheet URL: https://pim.murata.com/asset/pim4/ceramicCapacitorSMD/GRM0335C1H2R1BA01-01A-EN_PDF_CERAMICCAPACITORSMD?lastModifiedDatetime=20250813140603; Dielectric Type: C0G/NP0; Lead Time: 12; Mass: 0.00033g; Maximum Operating Temperature: +125DEGC; Maximum Tolerance: +0.1pF; Minimum Operating Temperature: -55DEGC; Minimum Tolerance: -0.1pF; Mounting Type: SMD; NOTEfied URL: https://webinterface.notefied-dynamic-precision.com/item/7272865; PCB Package: 0201; Packing Size: 50000; Packing Type: Tape & Reel; Part Number: 02-06135; Part Type: Capacitor|CERAMIC|0201|STANDARD; REACH/SVHC Compliance: Compliant; REACH/SVHC Details: SVHC List Version Jan 23, 2024 (240); REACH/SVHC Source: REACH Declaration; REACH/SVHC Status: Unaffected; ROHS: Compliant; Rated Voltage: 50V; Status: Released; Texas Part Status: Under Review; Type: Capacitor; Vendor: MURATA; Vendor Part Number: GRM0335C1H2R1BA01J; Vendor Part Status: Active
Z62 = CAPACITOR: CAPACITOR, CERAMIC C0G/NP0, 0.4pF, -0.05pF/+0.05pF, 25V, -55DEGC/+125DEGC, 0201, SMD; ALT_SYMBOLS: CAPC0603X35B2L,CAPC0603X35B2M; Additional Datasheet URL: https://pim.murata.com/en-us/pim/details?partNum=GRM0335C1ER40WA01%23; Budgetary Price: .00292 USD; Country of Origin: China, Japan, Philippines, Singapore, Thailand; Datasheet URL: https://pim.murata.com/asset/pim4/ceramicCapacitorSMD/GRM0335C1ER40WA01-01A-EN_PDF_CERAMICCAPACITORSMD?lastModifiedDatetime=20250813140522; Dielectric Type: C0G/NP0; Mass: 0.00033g; Maximum Operating Temperature: +125DEGC; Maximum Tolerance: +0.05pF; Minimum Operating Temperature: -55DEGC; Minimum Tolerance: -0.05pF; Mounting Type: SMD; NOTEfied URL: https://webinterface.notefied-dynamic-precision.com/item/54264192; PCB Package: 0201; Packing Size: 15000; Packing Type: Tape & Reel; Part Number: 02-11141; Part Type: Capacitor|CERAMIC|0201|STANDARD; REACH/SVHC Compliance: Compliant; REACH/SVHC Details: SVHC List Version Jan 23, 2024 (240); REACH/SVHC Source: REACH Declaration; REACH/SVHC Status: Unaffected; ROHS: Compliant; Rated Voltage: 25V; Status: Released; Texas Part Status: Under Review; Type: Capacitor; Vendor: MURATA; Vendor Part Number: GRM0335C1ER40WA01D; Vendor Part Status: Active

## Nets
GND: C9.2 C34.2 C52.2 C53.2 C81.2 C91.2 C92.2 C99.2 C101.2 C102.2 C103.2 C104.2 C105.2 C109.2 C110.2 C111.2 C114.2 C115.2 C116.2 C117.2 C118.2 C119.2 C120.2 C121.2 CR10.1 J7.1(GND) J7.2(GND) L34.2 U1.37(NC) U1.40(NC) U1.41(EGP) Y2.2 Y2.4 Z60.2 Z62.2 ; also on sheet 2 3 4
VDDR: C105.1 C118.1 C119.1 C120.1 C121.1 L1.1 U1.1(VDDR) U1.2(VDDR) U1.34(VDDR)
VDDS: B1.1 C99.1 C101.1 C103.1 C104.1 C110.1 C111.1 C114.1 C115.1 C117.1 R1.2 R93.2 U1.9(VDDIO) U1.17(VDDIO) U1.18(VDDS) U1.29(VDDS) U1.31(VDDS)
ANT: C33.1 L33.1 U1.39(ANT)
DIO0: U1.3(DIO0) ; also on sheet 2
DIO1: U1.4(DIO1) ; also on sheet 2 3
DIO2: U1.5(DIO2) ; also on sheet 2 3
DIO3: U1.6(DIO3) ; also on sheet 2
DIO4: U1.7(DIO4) ; also on sheet 2
DIO5: U1.8(DIO5) ; also on sheet 2
DIO7: U1.10(DIO7) ; also on sheet 2
DIO9_SWDIO: U1.11(DIO9_SWDIO) ; also on sheet 2 3
DIO10_SWDCK: U1.12(DIO10_SWDCK) ; also on sheet 2 3
DIO11: U1.13(DIO11) ; also on sheet 2
DIO12: U1.14(DIO12) ; also on sheet 2
DIO15: U1.15(DIO15) ; also on sheet 2
DIO16: U1.16(DIO16) ; also on sheet 2
DIO17: U1.19(DIO17_A8) ; also on sheet 2
DIO18: U1.20(DIO18_A7) ; also on sheet 2
DIO19: U1.21(DIO19_A6) ; also on sheet 2
DIO20: U1.22(DIO20_A5) ; also on sheet 2
DIO21: U1.23(DIO21_A4) ; also on sheet 2
DIO22: U1.24(DIO22_A3) ; also on sheet 2
DIO23: R6.2 ; also on sheet 2
DIO27: U1.32(DIO27_A1) ; also on sheet 2
DIO28: U1.33(DIO28_A0) ; also on sheet 2
RSTN: C92.1 R1.1 U1.25(nRST) ; also on sheet 2 3
WMCU_VDD: B1.2 ; also on sheet 2 3
X32N: C91.1 U1.27(DIO24_X32N) Y3.2
X32P: C81.1 R6.1 U1.26(DIO23_X32P) Y3.1
X48N: C52.1 U1.36(X48N) Y2.1
X48P: C53.1 U1.35(X48P) Y2.3
N3623105: C33.2 L34.1
N3644196: C34.1 L33.2 L35.1
N3644282: Z60.1 Z61.2
N3644474: CA2.2 Z61.1 Z62.1
N3645225: L1.2 U1.30(DCDC_SW)
N3645285: CA1.1 J7.3(SIG)
N3649908: C109.1 CA1.2 CA2.1 CR10.2 L35.2
N3995257: C9.1 U1.28(VDDD)
N4010002: C102.1 C116.1 R93.1 U1.38(VDDS)

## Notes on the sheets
sheet 1
- Wireless MCU RF
- Assemble CA1 OR CA2.
  CA1: Selects uFL
  CA2: Selects PCB antenna
- Pin 1
- Pin 2
- Pin 34
- PCB ANT
- Z60-Z62 for
  antenna matching
- Pin 18
- Pin 29
- Pin 31
- Pin 38
- Pin 28
- Pin 9
- Pin 17
- RF Frontend Filter Options
- Reference
  Designator
- CC2755R10
- CC2755P10
  CC2755P20
- Place L1, C105 & C121
  close to Pin 30
- C33
- 0.8 pF
- 0.8 pF
- L34
- 1.1 nH
- 1.2 nH
- L33
- 3.4 nH
- 3.3 nH
- C34
- 1.2 pF
- 1.6 pF
- L35
- 0 ohm
- 3.3 nH
- C109
- DNM
- 0.9 pF
- VDDS / VDDIO / VDDR Options
- CR10
- TPD1E0B04D
- DNM
- Reference
  Designator
- CC2755R10
- CC2755P10
  CC2755P20
- C101
- DNM
- 3.9 pF
- C102
- DNM
- 3.9 pF
- C111
- DNM
- 3.9 pF
- C115
- DNM
- 3.9 pF
- C117
- DNM
- 3.9 pF
- C121
- DNM
- 3.9 pF
- R93
- 0 ohm
- BLM03AX241SN1
